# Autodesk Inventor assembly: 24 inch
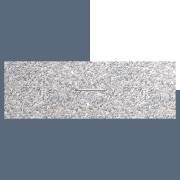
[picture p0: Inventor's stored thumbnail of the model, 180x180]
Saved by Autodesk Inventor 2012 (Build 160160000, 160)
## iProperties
Created: 2011-02
Part Number: 24 inch
Document SubType Name: Assembly
Designer: Beta-8540w
Author: Beta-8540w
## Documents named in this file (12)
- C:\Users\VMuser\Desktop\Inventor 2012 Essentials\Assemblies\Chapter 15\c15-04\c15-04-01.iam
- C:\Users\VMuser\Desktop\Inventor 2012 Essentials\Parts\Chapter 15\c15-11\c15-11-01.ipt
- C:\Inventor 2012 Essentials\Parts\Chapter 15\c15-11.ipt
- C:\Users\VMuser\Desktop\Inventor 2012 Essentials\Parts\Chapter 15\c15-12\c15-12-01.ipt
- C:\Inventor 2012 Essentials\Parts\Chapter 15\c15-12.ipt
- C:\Users\VMuser\Desktop\Inventor 2012 Essentials\Parts\Chapter 15\c15-13\c15-13-01.ipt
- C:\Inventor 2012 Essentials\Parts\Chapter 15\c15-13.ipt
- C:\Users\VMuser\Desktop\Inventor 2012 Essentials\Parts\Chapter 15\c15-15\c15-15-01.ipt
- C:\Inventor 2012 Essentials\Parts\Chapter 15\c15-15.ipt
- C:\Users\VMuser\Desktop\Inventor 2012 Essentials\Parts\Chapter 15\c15-16.ipt
- C:\Users\VMuser\Desktop\Inventor 2012 Essentials\Content Center Files\en-US\ANSI B18.6.3\ANSI B18.6.3 - 8-36 UNF - 0.875.ipt
- C:\Users\VMuser\Desktop\Inventor 2012 Essentials\Assemblies\Chapter 15\c15-04.iam
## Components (8 placed, 6 different names)
1. c15-11-01:1 — Mate:1, Flush:1, Mate:2, Mate:6, Mate:7, Wire Pull Insert 1, Wire Pull Insert 2, Wire Pull Screw constraint 1, Wire Pull Screw constraint 2, Mate:10, Mate:11
2. c15-12-01:1 — Flush:2, Mate:9, Flush:4, Flush:5, Flush:6
3. c15-13-01:1 — Mate:1, Flush:1, Mate:2, Flush:2, Mate:8, Mate:9, Flush:4, Flush:5
4. c15-13-01:2 — Flush:6, Mate:10, Mate:11
5. c15-15-01:1 — Mate:6, Mate:7, Mate:8
6. c15-16:1 — Wire Pull Insert 1, Wire Pull Insert 2
7. Cross Recessed Truss Head Machine Screw - Type IA - Inch No. 8 - 36 - 7/8:1 — Wire Pull Screw constraint 1
8. Cross Recessed Truss Head Machine Screw - Type IA - Inch No. 8 - 36 - 7/8:2 — Wire Pull Screw constraint 2
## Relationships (17: Mate 8, Flush 5, Insert 4)
- Mate:1: c15-11-01:1 ↔ c15-13-01:1
- Flush:1: c15-11-01:1 ↔ c15-13-01:1
- Mate:2: c15-11-01:1 ↔ c15-13-01:1
- Flush:2: c15-12-01:1 ↔ c15-13-01:1
- Mate:6: c15-11-01:1 ↔ c15-15-01:1
- Mate:7: c15-11-01:1 ↔ c15-15-01:1
- Mate:8: c15-13-01:1 ↔ c15-15-01:1
- Mate:9: c15-12-01:1 ↔ c15-13-01:1
- Flush:4: c15-12-01:1 ↔ c15-13-01:1
- Flush:5: c15-12-01:1 ↔ c15-13-01:1
- Wire Pull Insert 1 [Insert]: c15-11-01:1 ↔ c15-16:1
- Wire Pull Insert 2 [Insert]: c15-11-01:1 ↔ c15-16:1
- Wire Pull Screw constraint 1 [Insert]: c15-11-01:1 ↔ Cross Recessed Truss Head Machine Screw - Type IA - Inch No. 8 - 36 - 7/8:1
- Wire Pull Screw constraint 2 [Insert]: c15-11-01:1 ↔ Cross Recessed Truss Head Machine Screw - Type IA - Inch No. 8 - 36 - 7/8:2
- Flush:6: c15-12-01:1 ↔ c15-13-01:2
- Mate:10: c15-11-01:1 ↔ c15-13-01:2
- Mate:11: c15-11-01:1 ↔ c15-13-01:2
